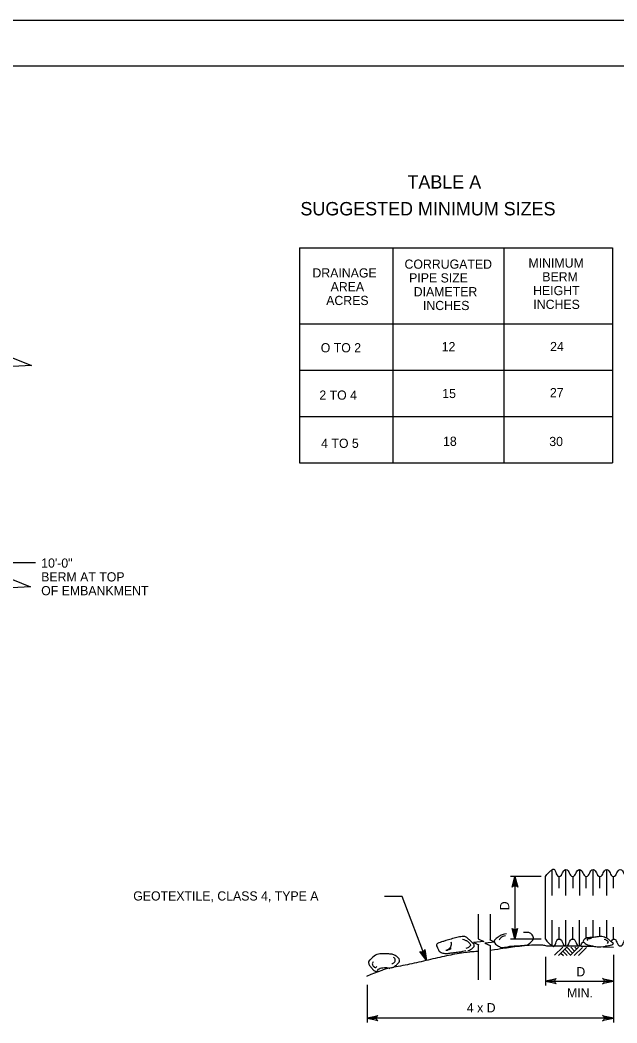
# Model space of a CAD drawing. Extents: x 636462 to 637367, y 299944 to 300538.
# Drawn here: x 636843.6 to 637038.2, y 300211.3 to 300538.4 of the extents above; entities that cross this region are included whole.
import ezdxf

# ---------------------------------------------------------------- set-up
doc = ezdxf.new("R2010")
doc.units = 0
for name, color, linetype in [('1', 7, 'Continuous'), ('Default', 7, 'Continuous'), ('PLT-BNDY', 7, 'Continuous')]:
    doc.layers.add(name, color=color, linetype=linetype)

# ---------------------------------------------------------------- blocks, each defined once
blk = doc.blocks.new('SC9446')
at = {"layer": 'Default'}
blk.add_line((0, 0), (0, 0), dxfattribs=at)

msp = doc.modelspace()

# ---------------------------------------------------------------- linework, layer by layer
at = {"layer": '1'}
msp.add_lwpolyline([(637287.91, 299959.45), (637287.91, 300523.45), (636501.91, 300523.45), (636501.91, 299959.45), (637287.91, 299959.45), (637287.91, 299985.81), (637087.91, 299985.81), (637087.91, 300050.49), (637287.91, 300050.49), (637287.91, 300079.45), (637087.91, 300079.45), (637087.91, 299959.45), (637166.72, 299959.45), (637166.72, 299985.81), (637166.72, 299959.45), (637243.72, 299959.45), (637243.72, 299985.81), (637243.72, 299973.49), (637287.91, 299973.49)], dxfattribs=at)
at = {"layer": 'Default'}
for p, q in [((636934.69, 300464.19), (637036.77, 300464.19)), ((636934.69, 300464.19), (636934.69, 300394.05)), ((636965.15, 300464.19), (636965.15, 300394.05)), ((637001.33, 300464.19), (637001.33, 300394.05)), ((637036.77, 300464.19), (637036.77, 300394.05)), ((636934.69, 300439.38), (637036.77, 300439.38)), ((636934.69, 300424.27), (637036.77, 300424.27)), ((636934.69, 300409.16), (637036.77, 300409.16)), ((636934.69, 300394.05), (637036.77, 300394.05)), ((637017.13, 300252.93), (637017.13, 300261.36)), ((637021.56, 300252.93), (637021.56, 300261.36)), ((637025.99, 300261.36), (637025.99, 300252.93)), ((637030.42, 300252.93), (637030.42, 300261.36)), ((637034.86, 300252.93), (637034.86, 300261.36)), ((637013.5, 300259.14), (637003.55, 300259.14)), ((637004.96, 300259.14), (637004.96, 300238.67)), ((637014.91, 300238.67), (637014.91, 300259.14)), ((637019.35, 300255.28), (637019.35, 300259.14)), ((637023.78, 300259.14), (637023.78, 300255.28)), ((637028.21, 300255.28), (637028.21, 300259.14)), ((637032.64, 300255.28), (637032.64, 300259.14)), ((637037.07, 300255.28), (637037.07, 300259.14)), ((636992.96, 300246.84), (636992.96, 300238.8)), ((636996.83, 300246.84), (636996.83, 300238.57)), ((637017.13, 300236.46), (637017.13, 300244.88)), ((637021.56, 300236.46), (637021.56, 300244.88)), ((637025.99, 300236.46), (637025.99, 300244.88)), ((637030.42, 300239.23), (637030.42, 300244.88)), ((637034.86, 300238.97), (637034.86, 300244.88)), ((637019.35, 300238.67), (637019.35, 300242.53)), ((637023.78, 300238.67), (637023.78, 300242.53)), ((637028.21, 300239), (637028.21, 300242.53)), ((637032.64, 300239.48), (637032.64, 300242.53)), ((637037.07, 300238.67), (637037.07, 300242.53)), ((637013.5, 300238.67), (637003.55, 300238.67)), ((636992.96, 300236.86), (636992.96, 300225.42)), ((636996.83, 300236.63), (636996.83, 300225.42)), ((637017.87, 300233.4), (637020.62, 300236.08)), ((637019.18, 300233.38), (637021.92, 300236.07)), ((637020.62, 300234.79), (637022.02, 300233.35)), ((637021.2, 300235.36), (637023.05, 300233.47)), ((637021.86, 300236.07), (637023.76, 300234.13)), ((637022.93, 300233.34), (637025.69, 300236.03)), ((637023.17, 300236.05), (637024.4, 300234.79)), ((637024.31, 300233.32), (637027.03, 300235.98)), ((637024.49, 300236.03), (637025.08, 300235.43)), ((637025.62, 300233.31), (637028.33, 300235.96)), ((637014.91, 300232.93), (637014.91, 300223.56)), ((637019.96, 300234.15), (637020.76, 300233.32)), ((637037.05, 300233.59), (637037.05, 300211.51)), ((637014.91, 300224.97), (637037.05, 300224.97)), ((636956.78, 300223.82), (636956.78, 300211.51)), ((637037.05, 300212.92), (636956.78, 300212.92))]:
    msp.add_line(p, q, dxfattribs=at)
for points in [[(636841.16, 300428.23), (636847.38, 300425.75), (636834.88, 300425.14), (636841.16, 300421.06)], [(636848.61, 300361.41), (636842.08, 300361.41), (636840.07, 300361.41), (636826.05, 300354.57)], [(636841.16, 300355.93), (636847.03, 300353.58), (636834.54, 300352.97), (636841.16, 300348.66)], [(637004.33, 300255.91), (637004.1, 300255.64), (637004.96, 300259.14), (637004.33, 300255.91), (637004.7, 300256.11), (637004.96, 300259.14), (637005.22, 300256.11), (637005.6, 300255.93), (637004.96, 300259.14), (637005.85, 300255.65), (637005.6, 300255.93)], [(636976.07, 300231.72), (636968.14, 300252.62), (636962.48, 300252.62)], [(637005.6, 300241.9), (637005.82, 300242.17), (637004.96, 300238.67), (637005.6, 300241.9), (637005.23, 300241.71), (637004.96, 300238.67), (637004.7, 300241.7), (637004.33, 300241.88), (637004.96, 300238.67), (637004.08, 300242.16), (637004.33, 300241.88)], [(636992.95, 300238.8), (636994.78, 300237.89), (636991.46, 300237.54), (636993.18, 300236.86)], [(636996.61, 300238.57), (636998.44, 300237.66), (636995.12, 300237.32), (636996.84, 300236.63)], [(636975.46, 300234.95), (636975.57, 300235.29), (636976.07, 300231.72), (636975.46, 300234.95), (636975.19, 300234.63), (636976.07, 300231.72), (636974.71, 300234.43), (636974.29, 300234.46), (636976.07, 300231.72), (636973.95, 300234.63), (636974.29, 300234.46)], [(637018.15, 300224.33), (637018.42, 300224.1), (637014.91, 300224.97), (637018.15, 300224.33), (637017.95, 300224.7), (637014.91, 300224.97), (637017.94, 300225.22), (637018.13, 300225.6), (637014.91, 300224.97), (637018.41, 300225.85), (637018.13, 300225.6)], [(637033.81, 300225.6), (637033.54, 300225.83), (637037.05, 300224.97), (637033.81, 300225.6), (637034.01, 300225.23), (637037.05, 300224.97), (637034.02, 300224.71), (637033.83, 300224.33), (637037.05, 300224.97), (637033.55, 300224.08), (637033.83, 300224.33)], [(636960.02, 300212.28), (636960.28, 300212.06), (636956.78, 300212.92), (636960.02, 300212.28), (636959.82, 300212.65), (636956.78, 300212.92), (636959.81, 300213.18), (636960, 300213.55), (636956.78, 300212.92), (636960.28, 300213.8), (636960, 300213.55)], [(637033.81, 300213.55), (637033.54, 300213.78), (637037.05, 300212.92), (637033.81, 300213.55), (637034.01, 300213.18), (637037.05, 300212.92), (637034.02, 300212.66), (637033.83, 300212.28), (637037.05, 300212.92), (637033.55, 300212.03), (637033.83, 300212.28)]]:
    msp.add_lwpolyline(points, dxfattribs=at)
for points in [[(637014.91, 300259.14), (637015.65, 300260.13), (637016.39, 300260.83), (637017.13, 300261.36), (637017.87, 300261.88), (637018.61, 300259.14), (637019.35, 300259.14), (637020.09, 300259.14), (637020.82, 300261.36), (637021.56, 300261.36), (637022.3, 300261.36), (637023.04, 300259.14), (637023.78, 300259.14), (637024.52, 300259.14), (637025.25, 300261.36), (637025.99, 300261.36), (637026.73, 300261.36), (637027.47, 300259.14), (637028.21, 300259.14), (637028.95, 300259.14), (637029.69, 300261.36), (637030.42, 300261.36), (637031.16, 300261.36), (637031.9, 300259.14), (637032.64, 300259.14), (637033.38, 300259.14), (637034.12, 300261.36), (637034.86, 300261.36), (637035.6, 300261.36), (637036.33, 300259.14), (637037.07, 300259.14), (637037.81, 300259.14), (637038.55, 300261.36), (637039.29, 300261.36), (637040.03, 300261.36), (637040.76, 300259.14), (637041.5, 300259.14), (637042.24, 300259.14), (637042.98, 300261.36), (637043.72, 300261.36), (637044.46, 300261.36), (637045.2, 300259), (637045.93, 300259.14), (637046.67, 300259.28), (637047.41, 300261.16), (637048.15, 300261.36), (637048.89, 300261.55), (637050.37, 300260.25), (637051.18, 300260.54), (637051.99, 300260.84), (637051.35, 300263.2), (637051.99, 300263.57), (637052.63, 300263.94), (637054.38, 300262.39), (637055.01, 300262.76), (637055.65, 300263.13), (637055.19, 300265.42), (637055.83, 300265.79), (637056.47, 300266.16), (637058.21, 300264.61), (637058.85, 300264.98), (637059.49, 300265.35), (637059.02, 300267.63), (637059.66, 300268), (637060.3, 300268.37), (637062.05, 300266.82), (637062.69, 300267.19), (637063.33, 300267.56), (637062.86, 300269.85), (637063.5, 300270.22), (637064.14, 300270.59), (637065.89, 300269.04), (637066.53, 300269.41), (637067.17, 300269.78), (637066.7, 300272.07), (637067.34, 300272.43), (637067.98, 300272.8), (637069.73, 300271.25), (637070.37, 300271.62), (637071.01, 300271.99), (637070.55, 300274.45), (637071.18, 300274.65), (637071.81, 300274.85), (637073.9, 300274.85), (637074.2, 300273.84)], [(637036.27, 300237.87), (637036.54, 300237.93), (637036.8, 300238.62), (637037.07, 300238.67), (637037.81, 300238.83), (637038.55, 300236.46), (637039.29, 300236.46), (637040.03, 300236.46), (637040.76, 300238.67), (637041.5, 300238.67), (637042.24, 300238.67), (637042.98, 300236.46), (637043.72, 300236.46), (637044.46, 300236.46), (637045.2, 300238.67), (637045.93, 300238.67), (637046.67, 300238.67), (637047.41, 300236.32), (637048.15, 300236.46), (637048.89, 300236.6), (637049.63, 300238.47), (637050.37, 300238.67), (637051.1, 300238.87), (637052.58, 300237.57), (637053.39, 300237.86), (637054.2, 300238.16), (637053.56, 300240.52), (637054.2, 300240.89), (637054.84, 300241.26), (637056.59, 300239.71), (637057.23, 300240.08), (637057.87, 300240.45), (637057.4, 300242.73), (637058.04, 300243.1), (637058.68, 300243.47), (637060.43, 300241.92), (637061.07, 300242.29), (637061.71, 300242.66), (637061.24, 300244.95), (637061.88, 300245.32), (637062.52, 300245.69), (637064.27, 300244.14), (637064.91, 300244.51), (637065.55, 300244.88), (637065.08, 300247.16), (637065.72, 300247.53), (637066.36, 300247.9), (637068.1, 300246.35), (637068.74, 300246.72), (637069.38, 300247.09), (637068.91, 300249.38), (637069.55, 300249.75), (637070.19, 300250.12), (637071.94, 300248.57), (637072.58, 300248.94), (637073.22, 300249.31), (637072.75, 300251.6), (637073.39, 300251.97), (637074.03, 300252.34), (637075.78, 300250.79), (637076.42, 300251.16), (637077.06, 300251.52), (637076.59, 300253.81), (637077.23, 300254.18), (637077.87, 300254.55), (637079.87, 300252.39), (637080.26, 300253.37), (637080.64, 300254.35), (637080.92, 300255.36), (637081.07, 300256.4)], [(636989.64, 300234.95), (636990.32, 300235.18), (636991.01, 300235.59), (636991.44, 300236.06), (636991.87, 300236.53), (636991.2, 300237.46), (636990.61, 300237.99), (636989.73, 300238.8), (636988.86, 300239.62), (636987.85, 300239.51), (636986.02, 300239.31), (636984.16, 300238.7), (636982.32, 300238.13), (636981.42, 300237.85), (636980.51, 300237.69), (636979.69, 300237.16), (636979.25, 300236.88), (636979.59, 300236.1), (636979.83, 300235.64), (636980.08, 300235.17), (636980.28, 300234.61), (636980.8, 300234.4), (636982.08, 300233.88), (636983.39, 300234.1), (636984.67, 300234.26), (636986.1, 300234.44), (636987.54, 300234.57), (636988.95, 300234.95)], [(636987.85, 300238.68), (636988.23, 300238.6), (636988.59, 300238.45), (636988.95, 300238.27), (636989.32, 300238.09), (636989.61, 300237.86), (636989.92, 300237.58), (636990.22, 300237.3), (636990.58, 300236.74), (636990.33, 300236.47), (636990, 300236.1), (636989.47, 300235.81), (636988.95, 300235.64)], [(637002.23, 300240.38), (637001.26, 300240.25), (637000.38, 300239.98), (636999.47, 300239.31), (636998.86, 300238.86), (636998.16, 300238.27), (636998.22, 300237.79), (636998.28, 300237.31), (636998.97, 300236.82), (636999.6, 300236.41), (637000.15, 300236.04), (637000.7, 300235.94), (637001.26, 300235.99), (637002.09, 300236.06), (637002.91, 300236.35), (637003.75, 300236.41), (637004.71, 300236.46), (637005.69, 300236.46), (637006.65, 300236.55), (637007.11, 300236.58), (637007.57, 300236.63), (637008.03, 300236.68)], [(637001.84, 300239.7), (637001.44, 300239.76), (637000.98, 300239.59), (637000.59, 300239.28), (637000.22, 300238.99), (636999.98, 300238.69), (636999.76, 300238.32)], [(637008.03, 300236.68), (637008.79, 300236.73), (637009.23, 300236.8), (637009.83, 300237.37), (637010.49, 300238.01), (637011.21, 300238.83), (637010.93, 300239.45), (637010.67, 300240.04), (637009.89, 300240.8), (637009.14, 300240.83), (637008.67, 300240.85), (637008.2, 300240.83), (637007.73, 300240.8)], [(637014.91, 300238.67), (637015.65, 300237.69), (637016.39, 300236.98), (637017.13, 300236.46), (637017.87, 300235.93), (637018.61, 300238.67), (637019.35, 300238.67), (637020.09, 300238.67), (637020.82, 300236.46), (637021.56, 300236.46), (637022.3, 300236.46), (637023.04, 300238.67), (637023.78, 300238.67), (637024.52, 300238.67), (637025.25, 300236.37), (637025.99, 300236.46), (637026.46, 300236.51), (637026.93, 300237.81), (637027.4, 300237.86)], [(637034.51, 300236.46), (637035.31, 300236.55), (637036.2, 300236.65), (637036.86, 300237.01), (637037.24, 300237.21), (637036.39, 300237.8), (637036.03, 300238.11), (637035.67, 300238.43), (637035.37, 300238.73), (637034.93, 300238.94), (637034.11, 300239.33), (637033.28, 300239.57), (637032.44, 300239.5), (637031.7, 300239.43), (637030.96, 300239.3), (637030.23, 300239.22), (637029.63, 300239.15), (637029.03, 300239.17), (637028.43, 300239.08), (637027.83, 300238.99), (637027.04, 300237.89), (637027.46, 300237.56), (637028.14, 300237.05), (637029.14, 300236.63), (637030.09, 300236.46), (637031.65, 300236.18), (637033.27, 300236.05), (637034.79, 300236.46)], [(637028.75, 300238.13), (637028.52, 300238.17), (637028.53, 300238.78), (637028.75, 300238.82), (637029.12, 300238.89), (637029.49, 300238.94), (637029.86, 300238.96)], [(637034, 300238.68), (637034.4, 300238.58), (637034.78, 300238.37), (637035.11, 300238.13), (637035.33, 300237.97), (637035.22, 300237.45), (637034.97, 300237.3)], [(636982.46, 300235.09), (636982.8, 300235), (636983.22, 300235.3), (636983.56, 300235.64), (636983.96, 300236.04), (636984.16, 300236.44), (636984.25, 300236.89), (636984.31, 300237.15), (636984.27, 300237.46), (636984.12, 300237.72)], [(636983.98, 300235.92), (636983.95, 300235.73), (636983.99, 300235.53), (636983.84, 300235.37), (636983.72, 300235.24), (636983.57, 300235.26), (636983.43, 300235.23), (636983.2, 300235.18), (636982.97, 300235.12), (636982.74, 300235.09)], [(637037.04, 300235.95), (637027.09, 300236.34), (637024.61, 300236.34), (637022.12, 300236.34), (637020.32, 300236.34), (637018.53, 300236.34), (637016.73, 300236.34), (637015.39, 300236.34), (637014.06, 300236.78), (637012.72, 300236.75), (637009.59, 300236.67), (637006.45, 300236.33), (637003.32, 300235.92), (637001.15, 300235.64), (636999, 300235.26), (636996.83, 300235.01)], [(636992.96, 300234.67), (636991.86, 300234.55), (636990.75, 300234.54), (636989.64, 300234.4), (636986.81, 300234.04), (636984.01, 300233.49), (636981.21, 300232.88), (636978.17, 300232.22), (636975.14, 300231.48), (636972.09, 300230.81), (636969.16, 300230.15), (636966.19, 300229.68), (636963.25, 300229.01), (636962.04, 300228.73), (636960.92, 300228.18), (636956.57, 300226.54)], [(636964.77, 300229.29), (636965.63, 300229.65), (636966.38, 300230.29), (636966.98, 300230.94), (636967.38, 300231.38), (636967.26, 300232.3), (636966.7, 300232.74), (636965.71, 300233.54), (636964.69, 300233.81), (636963.66, 300233.85), (636961.84, 300233.91), (636959.95, 300233.95), (636958.14, 300232.33), (636957.55, 300231.8), (636957.13, 300231.2), (636957.31, 300230.67), (636957.43, 300230.3), (636957.7, 300229.93), (636958, 300229.56), (636958.39, 300229.07), (636958.74, 300228.58), (636959.24, 300228.32), (636959.92, 300227.96), (636960.67, 300229.23), (636961.45, 300229.29), (636962.35, 300229.36), (636963.33, 300229.46), (636964.22, 300229.15)], [(636964.77, 300230.53), (636965.23, 300230.75), (636965.66, 300231.13), (636965.87, 300231.5), (636966.07, 300231.84), (636965.72, 300232.46), (636965.32, 300232.74)], [(636958.69, 300231.22), (636958.46, 300230.97), (636958.38, 300230.55), (636958.55, 300230.25), (636958.75, 300229.9), (636959.05, 300229.53), (636959.38, 300229.43), (636959.55, 300229.37), (636959.79, 300229.52), (636959.93, 300229.7)]]:
    msp.add_open_spline(points, degree=3, dxfattribs=at)
at = {"layer": 'PLT-BNDY'}
msp.add_lwpolyline([(636461.91, 300538.45), (637302.91, 300538.45), (637302.91, 299944.45), (636461.91, 299944.45)], close=True, dxfattribs=at)

# ---------------------------------------------------------------- block references
at = {"layer": 'Default', "xscale": 2.2030652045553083, "yscale": 2.2030652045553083}
for p in [(637025.99, 300244.88), (636996.83, 300235.01), (636992.96, 300234.67)]:
    msp.add_blockref('SC9446', p, dxfattribs=at)

# ---------------------------------------------------------------- texts
at = {"layer": 'Default'}
for s, height, p in [('TABLE A', 4.372, (636969.91, 300483.47)), ('SUGGESTED MINIMUM SIZES', 4.3721, (636935.02, 300474.73)), ('MINIMUM', 2.998, (637009.37, 300457.71)), ('DRAINAGE', 2.998, (636938.94, 300454.48)), ('CORRUGATED', 2.998, (636968.96, 300457.34)), ('PIPE SIZE', 2.998, (636970.47, 300452.85)), ('BERM', 2.998, (637013.87, 300453.22)), ('AREA', 2.998, (636944.87, 300449.98)), ('DIAMETER', 2.998, (636971.96, 300448.35)), ('HEIGHT', 2.998, (637010.88, 300448.72)), ('ACRES', 2.998, (636943.43, 300445.49)), ('INCHES', 2.998, (636974.97, 300443.85)), ('INCHES', 2.998, (637010.96, 300444.22)), ('O TO 2', 2.998, (636941.65, 300430.07)), ('12', 2.998, (636981.08, 300430.43)), ('24', 2.998, (637016.43, 300430.46)), ('15', 2.998, (636981.26, 300415.16)), ('27', 2.998, (637016.36, 300415.43)), ('2 TO 4', 2.998, (636941.2, 300414.62)), ('4 TO 5', 2.998, (636941.79, 300398.91)), ('18', 2.998, (636981.52, 300399.56)), ('30', 2.998, (637016.15, 300399.5)), ('10\'-0"', 2.998, (636850.52, 300359.84)), ('BERM AT TOP', 2.998, (636850.52, 300355.34)), ('OF EMBANKMENT', 2.998, (636850.52, 300350.84)), ('GEOTEXTILE, CLASS 4, TYPE A', 2.998, (636880.53, 300251.27)), ('D', 3, (637024.98, 300226.55)), ('MIN.', 2.998, (637021.92, 300219.68)), ('4 x D', 2.998, (636989.28, 300214.81))]:
    msp.add_text(s, height=height, dxfattribs=at).set_placement(p)
msp.add_text('D', height=3, rotation=90, dxfattribs=at).set_placement((637003.09, 300248.09))

doc.saveas('drawing.dxf')
